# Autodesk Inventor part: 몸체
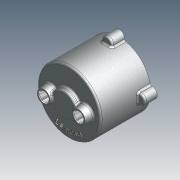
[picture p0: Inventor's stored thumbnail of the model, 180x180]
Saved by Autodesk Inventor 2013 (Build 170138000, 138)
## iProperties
Company: 한국ATC센터
Created: 2012-05
Part Number: 몸체
Document SubType Name: 모델링
Designer: KYOUNG IL JANG
Mass: 471.062 g
Surface Area: 679.308 cm^2
Volume: 173.824 cm^3
Density: 2.71 g/cm^3
Material: 알루미늄-6061
변환 표준: STEP AP214IS
파일 이름: C:\Users\SeoGD\Desktop\?쒗뿕\紐몄껜.stp
전처리기: Build: 253, Release: 2010 SP1 - Date: Wed 07/29/2009
전송 단위: 밀리미터
불확실성: 0.01
Author: KYOUNG IL JANG
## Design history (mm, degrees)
sketch "스케치2"
  geometry: C1 r 50 at (0, 0); 1 further point
  constraints: 1 centre point, 1 coincident
  dimensions: "d9" = 100 diameter of C1
extrude "돌출2" new body sketch "스케치2" distance "d10" = 80; taper "d11" = 0 deg
feature "쉘1" dims "d12" = 5
sketch "스케치3" dims "d13" = 55
  geometry: C1 r 7.5 at (27.5, 0); C2 r 12.5 at (27.5, 0); 2 further points
  constraints: 2 centre point, 2 coincident, 2 horizontal alignment, 2 other
  dimensions: "d14" = 15 diameter of C1; "d15" = 25 diameter of C2
extrude "돌출3" join sketch "스케치3" distance "d16" = 12; taper "d17" = -10 deg
hole "구멍2" diameter "d20" = 15; stored, may be unused: countersink angle "d24" = 90 deg, drill point angle "d26" = 118 deg; dims "d18" = 10, "d19" = 10, "d21" = 6, "d22" = 4, "d23" = 2, "d25" = 15
chamfer "모따기1" distance "d27" = 1; stored, may be unused: second distance "d28" = 2, angle "d29" = 45 deg
sketch "스케치4"
  geometry: L1 (0, 0)-(0, 88); L2 (0, 70)-(13.16, 70); L3 (-45, 75)-(45, 75) reference; L4 (-50, 80)-(50, 80) reference; L5 (13.16, 70)-(14.5, 75); L6 (20, 80)-(20, 88); L7 (20, 88)-(0, 88); L8 (20, 80)-(14.5, 75)
  constraints: 12 end point, 3 point on line, 2 perpendicular, 1 vertical
  dimensions: "d34" = 40 diameter of L6 L1; "d35" = 105 deg angle of L5 L3; "d36" = 5 distance between parallel lines of L2 L3; "d37" = 8 distance between parallel lines of L7 L4; "d51" = 29 diameter of L5.end L1
revolve "회전1" sketch "스케치4" stored, may be unused: angle "d38" = 90 deg
hole "구멍3" diameter "d41" = 15; stored, may be unused: countersink angle "d45" = 90 deg, drill point angle "d47" = 0 deg; dims "d39" = 10, "d40" = 10, "d42" = 6, "d43" = 22, "d44" = 13, "d46" = 15
chamfer "모따기2" distance "d48" = 1; stored, may be unused: second distance "d49" = 2, angle "d50" = 45 deg
fillet "모깎기1" dims "d52" = 3
fillet "모깎기2" dims "d53" = 3, "d72" = 0.2
sketch "스케치5"
  geometry: A1 r 50 centre (0, 0) between (50, 0) and (-8.074, 49.344) reference; A2 r 8.5 centre (0, 52) between (8.074, 49.344) and (-8.074, 49.344); 1 further point
  constraints: 5 point on circle, 1 centre point, 1 horizontal alignment
  dimensions: "d54" = 90 deg dimension on point (0, 0) A2.centre A1.start; "d55" = 52 distance of A2.centre point (0, 0); "d56" = 17 diameter of A2
extrude "돌출4" join sketch "스케치5" distance "d57" = 20; taper "d58" = 0 deg
fillet "모깎기3" dims "d59" = 3
hole "구멍4" diameter "d62" = 4.134; stored, may be unused: countersink angle "d66" = 90 deg, drill point angle "d68" = 118 deg; dims "d60" = 10, "d61" = 10, "d63" = 12, "d64" = 22, "d65" = 13, "d67" = 15
sketch "스케치6"
  geometry: C1 r 47 at (0, 0) reference; C2 r 42.5 at (0, 0); 1 further point
  constraints: 1 centre point, 1 coincident, 1 other
  dimensions: "d73" = 85 diameter of C2
feature "엠보싱1" sketch "스케치6" dims "d74" = 1, "d75" = 0
node "솔리드1"
node "솔리드 본체"
node "곡면 본체"
pattern_circular "원형 패턴1" dims "d31" = 360 deg
pattern_circular "원형 패턴2" dims "d70" = 360 deg
node "솔리드2"
